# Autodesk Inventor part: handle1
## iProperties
Author: Administrator
Created: 2001-03
Part Number: handle1
Document SubType Name: Modeling
Designer: Administrator
Control State: 0
Master: False
Checked Out: False
PropertySet Name: Design Tracking Control
Shininess: 20.0
PropertySet Name: _Private Model Information
Density: 0.0
Volumn: 0.0
Area: 0.0
PropertySet Name: Model Information
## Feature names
1. Extrusion1
2. Extrusion2
3. Extrusion3
4. Fillet1
5. Fillet2
6. d_cut [Extrusion]
7. Extrusion5
8. Fillet3
